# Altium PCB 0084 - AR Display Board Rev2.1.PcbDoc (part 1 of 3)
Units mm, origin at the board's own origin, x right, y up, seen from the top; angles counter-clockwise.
Board outline 127.7 x 27.2 mm, 4 copper layers (L1-TOP, L2-GND, L3-GND, L4-BOT), stack 1.571 mm thick; 141 components, 141 nets, 671 pads, 447 vias.
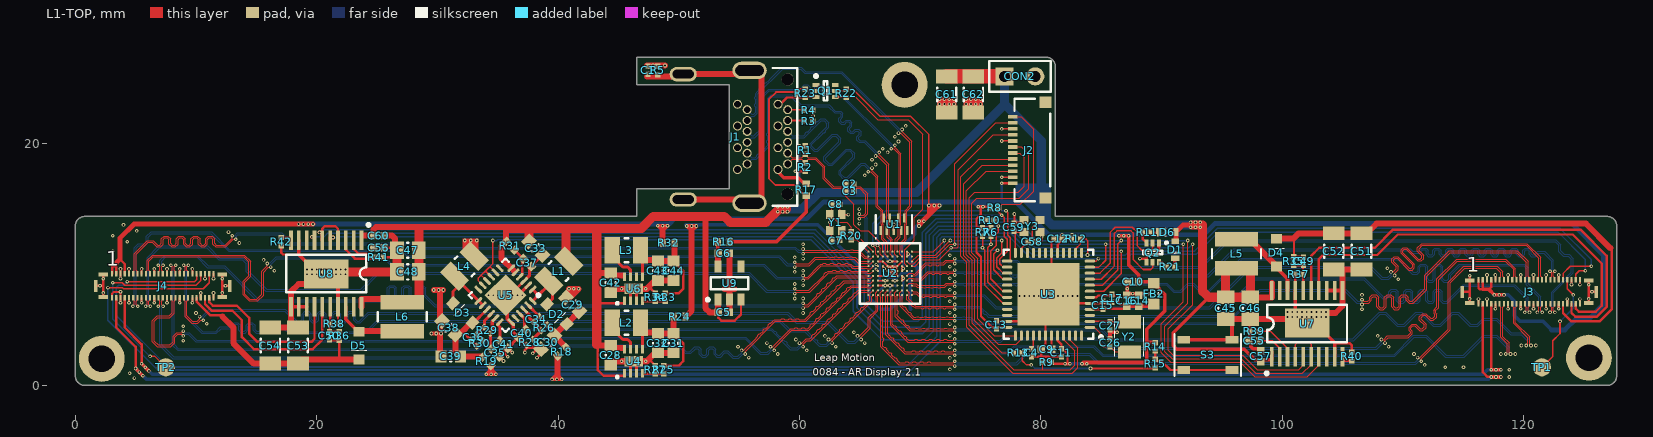
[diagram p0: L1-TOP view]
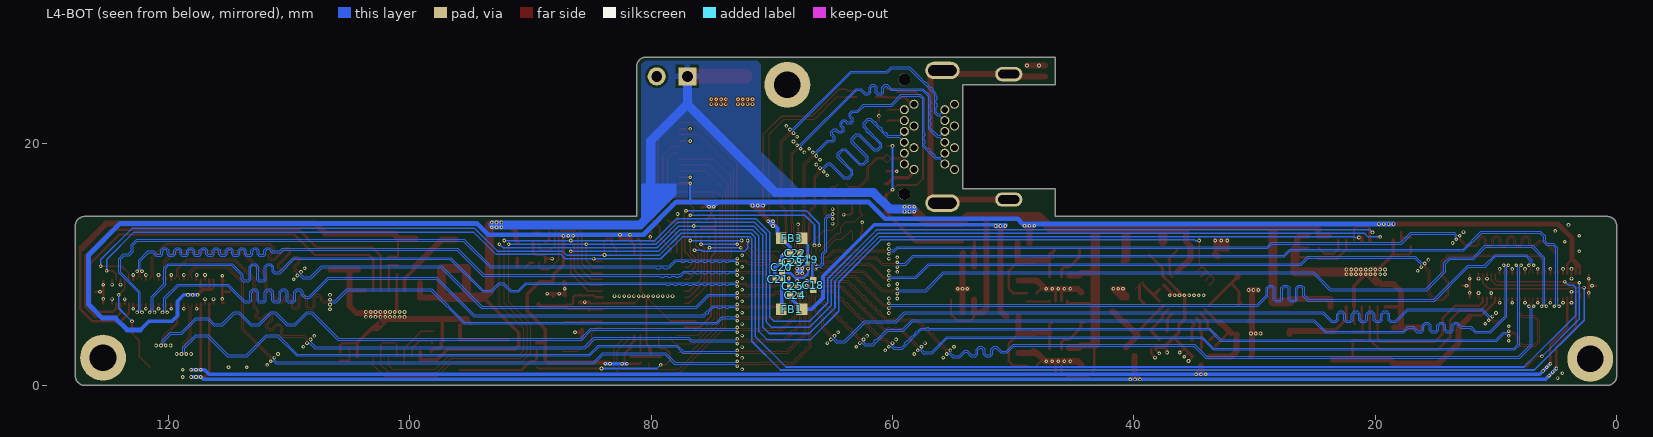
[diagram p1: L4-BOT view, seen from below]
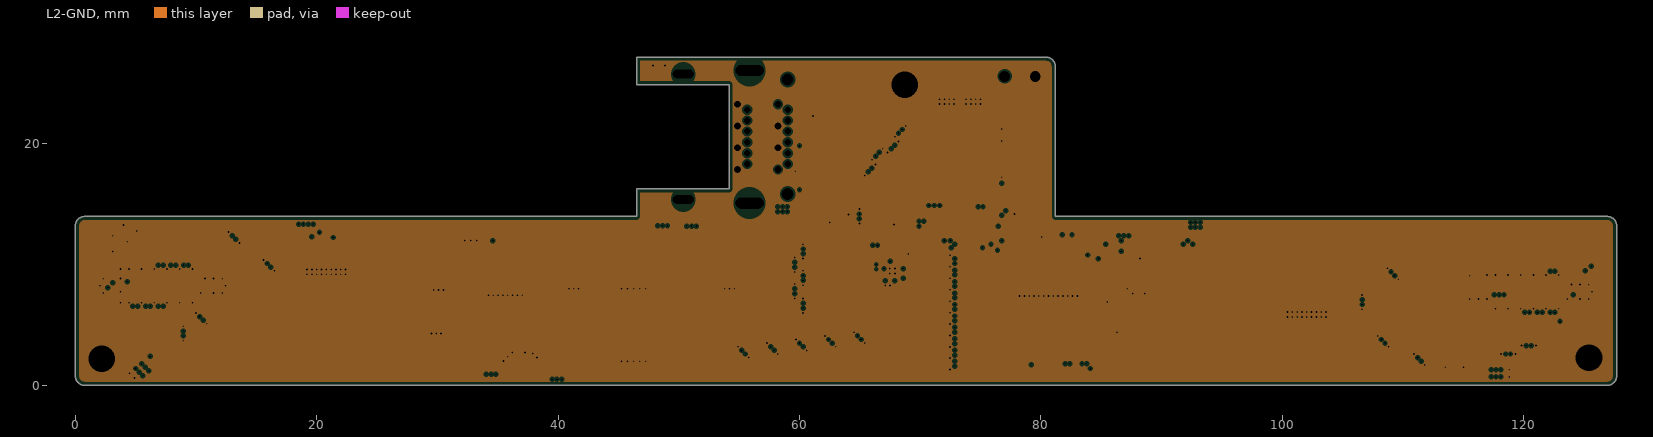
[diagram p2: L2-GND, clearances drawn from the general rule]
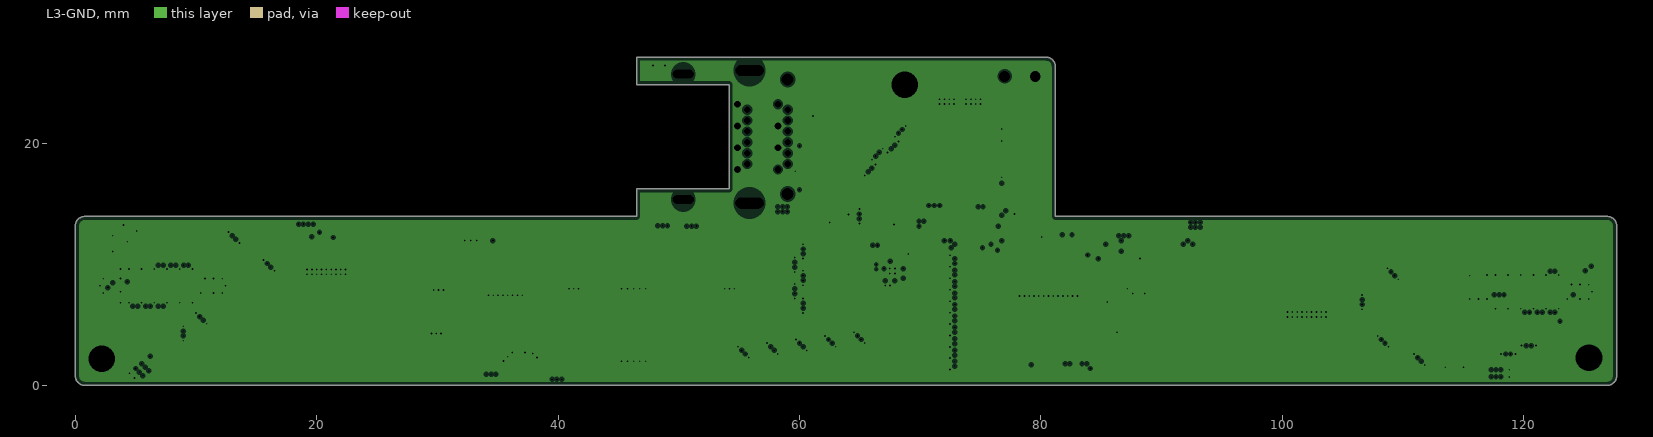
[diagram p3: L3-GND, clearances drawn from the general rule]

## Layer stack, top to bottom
Top Solder: solder mask 0.0102, Solder Resist, Dk 3.5
L1-TOP: signal copper 0.035
Dielectric1: core 0.175, FR-4, Dk 4.2
L2-GND: plane copper 0.036, net GND
Dielectric2: prepreg 1, Dk 4.2
L3-GND: plane copper 0.036, net GND
Dielectric 3: core 0.254, Dk 4.2
L4-BOT: signal copper 0.035
Bottom Solder: solder mask 0.0102, Solder Resist, Dk 3.5

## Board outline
0.8,0 cw(c0.8,0.8) 0,0.8 0,13.2 cw(c0.8,13.2) 0.8,14 46.5,14 46.5,16.3 54.16,16.3 54.16,24.9 46.5,24.9 46.5,27.2 80.4,27.2 cw(c80.4,26.4) 81.2,26.4 81.2,14 126.9,14 cw(c126.9,13.2) 127.7,13.2 127.7,0.8 cw(c126.9,0.8) 126.9,0

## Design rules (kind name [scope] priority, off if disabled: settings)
Clearance Clearance_1 [InComponent('CON2')] p1: gap=0.2
Clearance dp [(InDifferentialPairClass('All Differential Pairs')) vs InNet('GND')] p2: gap=0.076
Clearance [All] p3: gap=0.076
DiffPairsRouting [All] p1: maxlimit=0.076 minlimit=0.076 mostfreqgap=0.076 toplayer_minwidth=0.076 toplayer_maxwidth=0.076 toplayer_prefwidth=0.076 bottomlayer_minwidth=0.076 bottomlayer_maxwidth=0.076 bottomlayer_prefwidth=0.076 maxuncoupledlength=12.7
HoleSize [All] p1: absolutevalues=TRUE maxlimit=2.54 minlimit=0.1 maxpercent=80.000 minpercent=20.000
HoleToHoleClearance [All] p1: gap=0.25 allowstackedmicrovias=TRUE
MatchedLengths ML_MIPI_R [InNetClass('MIPI_R')] p1: tolerance=0.025 checknetsindiffpair=TRUE checkdiffpairvsdiffpair=TRUE checkothers=TRUE
MatchedLengths ML_MIPI_L [InNetClass('MIPI_L')] p2: tolerance=0.025 checknetsindiffpair=TRUE checkdiffpairvsdiffpair=TRUE checkothers=TRUE
MatchedLengths ML_DP_LANE [InNetClass('DP_LANE')] p3: tolerance=0.025 checknetsindiffpair=TRUE checkdiffpairvsdiffpair=TRUE checkothers=TRUE
MinimumAnnularRing [All] p1: minimumring=0.074
MinimumSolderMaskSliver [All] p1: minsoldermaskwidth=0.076
PlaneClearance [All] p1: clearance=0.15
PlaneConnect [All] p1: planeconnectstyle=Direct reliefexpansion=0 reliefentries=4 reliefconductorwidth=0.15 reliefairgap=0.15
PolygonConnect PolygonConnect_2 [InNet('GND') And OnLayer('L4-BOT')] p1: connectstyle=Relief reliefconductorwidth=0.254 reliefentries=4 polygonreliefangle="90 Angle" airgapwidth=0.254
PolygonConnect PolygonConnect_1 [InNet('5V') And OnLayer('L4-BOT')] p2: connectstyle=Relief reliefconductorwidth=0.5 reliefentries=4 polygonreliefangle="90 Angle" airgapwidth=0.2
PolygonConnect [All] p3: connectstyle=Direct reliefconductorwidth=0.254 reliefentries=4 polygonreliefangle="90 Angle" airgapwidth=0.254
RoutingVias [All] p1: holewidth=0.15 width=0.3 viastyle="Through Hole" minholewidth=0.15 minwidth=0.3 maxholewidth=0.711 maxwidth=1.27
SilkToSilkClearance [All] p1: silktosilkclearance=0.2
SilkToSolderMaskClearance SilkscreenOverComponentPads [IsPad] p1: minsilkscreentomaskgap=0.1 clearancetoexposedcopper=FALSE
SolderMaskExpansion [All] p1: expansion=0.025
UnpouredPolygon [All] p1: allowunpoured=FALSE
Width [All] p1: maxlimit=5 minlimit=0.076 preferedwidth=0.2 minimp=50.000000 maximp=50.000000 favimp=50.000000
21 further rules are at their usual default settings.

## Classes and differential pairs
component class "0084 - Connectors": C1 C61 C62 CON2 J1 J2 J3 J4 R1 R2 R3 R4 R5 R17 TP1 TP2 U1
component class "0084 - MCU": C2 C3 C4 C7 C8 C9 C10 C11 C12 C13 C14 C15 C16 C17 C18 C19 C20 C21 C22 C23 C24 C25 C26 C27 C58 C59 D1 D6 FB1 FB2 FB3 Q1 Q2 R6 R7 R8 R9 R10 R11 R12 R13 R14 R15 R20 R21 R22 R23 S3 U2 U3 Y1 Y2 Y3
component class "0084 - Power": C5 C6 C28 C29 C30 C31 C32 C33 C34 C35 C36 C37 C38 C39 C40 C41 C42 C43 C44 C45 C46 C47 C48 C49 C50 C51 C52 C53 C54 C55 C56 C57 C60 D2 D3 D4 D5 L1 L2 L3 L4 L5 L6 R16 R18 R19 R24 R25 R26 R27 R28 R29 R30 R31 R32 R33 R34 R35 R36 R37 R38 R39 R40 R41 R42 U4 U5 U6 U7 U8 U9
net class MIPI_R: MIPI_DSI10_0_N MIPI_DSI10_0_P MIPI_DSI10_1_N MIPI_DSI10_1_P MIPI_DSI10_2_N MIPI_DSI10_2_P MIPI_DSI10_3_N MIPI_DSI10_3_P MIPI_DSI10_C_N MIPI_DSI10_C_P MIPI_DSI11_0_N MIPI_DSI11_0_P MIPI_DSI11_1_N MIPI_DSI11_1_P MIPI_DSI11_2_N MIPI_DSI11_2_P MIPI_DSI11_3_N MIPI_DSI11_3_P MIPI_DSI11_C_N MIPI_DSI11_C_P
net class MIPI_L: MIPI_DSI00_0_N MIPI_DSI00_0_P MIPI_DSI00_1_N MIPI_DSI00_1_P MIPI_DSI00_2_N MIPI_DSI00_2_P MIPI_DSI00_3_N MIPI_DSI00_3_P MIPI_DSI00_C_N MIPI_DSI00_C_P MIPI_DSI01_0_N MIPI_DSI01_0_P MIPI_DSI01_1_N MIPI_DSI01_1_P MIPI_DSI01_2_N MIPI_DSI01_2_P MIPI_DSI01_3_N MIPI_DSI01_3_P MIPI_DSI01_C_N MIPI_DSI01_C_P
net class DP_LANE: DP_LANE0_N DP_LANE0_P DP_LANE1_N DP_LANE1_P DP_LANE2_N DP_LANE2_P DP_LANE3_N DP_LANE3_P
net class AUX: DP_AUX_CH_N DP_AUX_CH_P
differential pair AUX: +AUX_P -AUX_N
differential pair DP_AUX_CH: +DP_AUX_CH_P -DP_AUX_CH_N
differential pair DP_LANE0: +DP_LANE0_P -DP_LANE0_N
differential pair DP_LANE1: +DP_LANE1_P -DP_LANE1_N
differential pair DP_LANE2: +DP_LANE2_P -DP_LANE2_N
differential pair DP_LANE3: +DP_LANE3_P -DP_LANE3_N
differential pair MIPI_DSI00_0: +MIPI_DSI00_0_P -MIPI_DSI00_0_N
differential pair MIPI_DSI00_1: +MIPI_DSI00_1_P -MIPI_DSI00_1_N
differential pair MIPI_DSI00_2: +MIPI_DSI00_2_P -MIPI_DSI00_2_N
differential pair MIPI_DSI00_3: +MIPI_DSI00_3_P -MIPI_DSI00_3_N
differential pair MIPI_DSI00_C: +MIPI_DSI00_C_P -MIPI_DSI00_C_N
differential pair MIPI_DSI01_0: +MIPI_DSI01_0_P -MIPI_DSI01_0_N
differential pair MIPI_DSI01_1: +MIPI_DSI01_1_P -MIPI_DSI01_1_N
differential pair MIPI_DSI01_2: +MIPI_DSI01_2_P -MIPI_DSI01_2_N
differential pair MIPI_DSI01_3: +MIPI_DSI01_3_P -MIPI_DSI01_3_N
differential pair MIPI_DSI01_C: +MIPI_DSI01_C_P -MIPI_DSI01_C_N
differential pair MIPI_DSI10_0: +MIPI_DSI10_0_P -MIPI_DSI10_0_N
differential pair MIPI_DSI10_1: +MIPI_DSI10_1_P -MIPI_DSI10_1_N
differential pair MIPI_DSI10_2: +MIPI_DSI10_2_P -MIPI_DSI10_2_N
differential pair MIPI_DSI10_3: +MIPI_DSI10_3_P -MIPI_DSI10_3_N
differential pair MIPI_DSI10_C: +MIPI_DSI10_C_P -MIPI_DSI10_C_N
differential pair MIPI_DSI11_0: +MIPI_DSI11_0_P -MIPI_DSI11_0_N
differential pair MIPI_DSI11_1: +MIPI_DSI11_1_P -MIPI_DSI11_1_N
differential pair MIPI_DSI11_2: +MIPI_DSI11_2_P -MIPI_DSI11_2_N
differential pair MIPI_DSI11_3: +MIPI_DSI11_3_P -MIPI_DSI11_3_N
differential pair MIPI_DSI11_C: +MIPI_DSI11_C_P -MIPI_DSI11_C_N

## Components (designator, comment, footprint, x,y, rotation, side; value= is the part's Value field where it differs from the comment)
C1 "0.1uF" CAPC0201(0603)33_N 47.46,26.1 r270 top
C2 "0.1uF" CAPC0201(0603)33_N 64.16,16.7 r180 top
C3 "0.1uF" CAPC0201(0603)33_N 64.16,16.1 r180 top
C4 "0.1uF" CAPC0201(0603)33_N 79.2,2.7 r90 top
C5 "1.0uF" CAPC0402(1005)60_N 53.725,6.05 r0 top
C6 "1.0uF" CAPC0402(1005)60_N 53.725,10.95 r0 top
C7 "6pF" CAPC0201(0603)33_N 63,12 r180 top
C8 "6pF" CAPC0201(0603)33_N 63,15 r0 top
C9 "2.2uF" CAPC0402(1005)60_N 80.46,3 r180 top
C10 "1.0uF" CAPC0402(1005)60_N 87.66,8.6 r0 top
C11 "0.1uF" CAPC0201(0603)33_N 81.7,2.7 r90 top
C12 "0.1uF" CAPC0201(0603)33_N 81.425,12.15 r0 top
C13 "0.1uF" CAPC0201(0603)33_N 76.3,5.025 r270 top
C14 "1.0uF" CAPC0402(1005)60_N 88.1,7 r270 top
C15 "0.1uF" CAPC0201(0603)33_N 85.125,6.625 r270 top
C16 "1.0uF" CAPC0402(1005)60_N 87.1,7 r270 top
C17 "0.1uF" CAPC0201(0603)33_N 85.9,7.2 r90 top
C18 "1.0uF" CAPC0402(1005)60_L 66.56,8.3 r90 bottom
C19 "0.1uF" CAPC0201(0603)33_L 67.01,10.4 r90 bottom
C20 "1.0uF" CAPC0402(1005)60_L 69.16,9.8 r270 bottom
C21 "0.1uF" CAPC0201(0603)33_L 69.46,8.8 r180 bottom
C22 "1.0uF" CAPC0402(1005)60_L 68.06,10.95 r0 bottom
C23 "0.1uF" CAPC0201(0603)33_L 68.26,10.2 r0 bottom
C24 "1.0uF" CAPC0402(1005)60_L 68.06,7.45 r0 bottom
C25 "0.1uF" CAPC0201(0603)33_L 68.26,8.2 r0 bottom
C26 "18pF" CAPC0201(0603)33_N 85.725,3.55 r90 top
C27 "18pF" CAPC0201(0603)33_N 85.725,4.95 r270 top
C28 "10uF" CAPC0603(1608)100_N 44.36,2.5 r90 top
C29 "10uF" CAPC0603(1608)100_N 41.2,6.7 r315 top
C30 "10uF" CAPC0603(1608)100_N 39.144,3.567 r45 top
C31 "10uF" CAPC0603(1608)100_N 49.56,3.5 r90 top
C32 "10uF" CAPC0603(1608)100_N 48.26,3.5 r90 top
C33 "10uF" CAPC0603(1608)100_N 38.144,11.367 r135 top
C34 "15pF" CAPC0201(0603)33_N 38.19,5.487 r225 top
C35 "1.0uF" CAPC0402(1005)60_N 34.8,2.7 r315 top
C36 "12pF" CAPC0201(0603)33_N 33,4 r45 top
C37 "1.0uF" CAPC0402(1005)60_N 37.444,10.167 r135 top
C38 "10uF" CAPC0603(1608)100_N 30.944,4.767 r315 top
C39 "10uF" CAPC0603(1608)100_N 31.1,2.4 r0 top
C40 "10nF" CAPC0402(1005)60_N 37,4.3 r225 top
C41 "4.7nF" CAPC0402(1005)60_N 35.5,3.4 r315 top
C42 "10uF" CAPC0603(1608)100_N 44.36,8.5 r90 top
C43 "10uF" CAPC0603(1608)100_N 48.26,9.5 r90 top
C44 "10uF" CAPC0603(1608)100_N 49.56,9.5 r90 top
C45 "47uF" CAPC0805(2012)100_N 95.3,6.4 r90 top
C46 "47uF" CAPC0805(2012)100_N 97.35,6.4 r90 top
C47 "47uF" CAPC0805(2012)100_N 27.56,11.2 r0 top
C48 "47uF" CAPC0805(2012)100_N 27.56,9.4 r0 top
C49 "18pF" CAPC0201(0603)33_N 101.76,10.3 r270 top
C50 "18pF" CAPC0201(0603)33_N 21.06,4.1 r90 top
C51 "10uF" CAPC1206(3216)170_N 106.56,11.1 r90 top
C52 "10uF" CAPC1206(3216)170_N 104.26,11.1 r90 top
C53 "10uF" CAPC1206(3216)170_N 18.46,3.3 r270 top
C54 "10uF" CAPC1206(3216)170_N 16.16,3.3 r270 top
C55 "1.0uF" CAPC0402(1005)60_N 97.66,3.7 r180 top
C56 "1.0uF" CAPC0402(1005)60_N 25.16,11.4 r0 top
C57 "1.0uF" CAPC0402(1005)60_N 98.2,2.4 r270 top
C58 "12pF" CAPC0201(0603)33_N 79.26,11.9 r0 top
C59 "12pF" CAPC0201(0603)33_N 77.76,13.1 r90 top
C60 "1.0uF" CAPC0402(1005)60_N 25.16,12.4 r180 top
C61 "10uF" CAPC1206(3216)170_N 72.2,24.1 r90 top
C62 "10uF" CAPC1206(3216)170_N 74.4,24.1 r90 top
CON2 "CON2" CON2_100mil 78.26,25.6 r0 top
D1 "Value" Dialight_598-8010-107F 91.132,11.225 r270 top
D2 "SCHOTTKY" Toshiba_CUS10S40,H3F#1 39.9,5.9 r315 top
D3 "SCHOTTKY" Toshiba_CUS10S40,H3F#2 32.1,6 r315 top
D4 "SCHOTTKY" Toshiba_CUS10S40,H3F#2 99.5,11 r270 top
D5 "SCHOTTKY" Toshiba_CUS10S40,H3F#2 23.5,3.3 r90 top
D6 "Value" Dialight_598-8040-107F 90.475,12.7 r180 top
FB1 "Ferrite Bead" INDC1608X09N 68.36,6.3 r0 bottom
FB2 "Ferrite Bead" INDC1608X09N 89.36,7.6 r270 top
FB3 "Ferrite Bead" INDC1608X09N 68.36,12.2 r180 bottom
J1 "TE_2129320-3" TE_2129320-3 53.26,20.59 r270 top
J2 "FCI 10051922-1210ELF" "FCI 10051922-1210ELF" 79.51,19.5 r90 top locked
J3 "Kyocera_245863050024829" Kyocera_245863050024829 120.45,7.75 r0 top (schematic designator J2)
J4 "Kyocera_245863050024829" Kyocera_245863050024829 7.25,8.25 r0 top (schematic designator J2)
L1 "4.7uH" INDC2520X10N 40.044,9.467 r225 top
L2 "1uH" INDC2520X10N 45.66,5.2 r0 top
L3 "1uH" INDC2520X10N 45.66,11.2 r0 top
L4 "4.7uH" INDC2520X10N 32.244,9.867 r45 top
L5 "15uH" Coilcraft_XAL4040-153MEB 96.2,10.9 r90 top
L6 "15uH" Coilcraft_XAL4040-153MEB 27.1,5.7 r270 top
Q1 "NFET_DUAL" SOT-563 62.16,24.4 r0 top
Q2 "NFET_DUAL" SOT-563 89.26,11 r270 top
R1 "1M" RESC0201(0603)_N#1 60.46,19.49 r90 top
R2 "1M" RESC0201(0603)_N#2 60.46,18.09 r270 top
R3 "1M" RESC0201(0603)_N#1 60.76,21.9 r180 top
R4 "1M" RESC0201(0603)_N#1 60.76,22.8 r180 top
R5 "1M" RESC0201(0603)_N#1 48.26,26.1 r270 top
R6 "4.7K" RESC0201(0603)_N#1 75.86,12.7 r90 top
R7 "4.7K" RESC0201(0603)_N#1 75.16,12.7 r90 top
R8 "10K" RESC0201(0603)_N#1 76.16,14.7 r180 top
R9 "10K" RESC0201(0603)_N#1 80.5,1.9 r0 top
R10 "10K" RESC0201(0603)_N#1 75.76,13.7 r180 top
R11 "1K" RESC0201(0603)_N#1 88.8,12.675 r180 top
R12 "10K" RESC0201(0603)_N#1 82.925,12.15 r180 top
R13 "1K" RESC0201(0603)_N#1 78.1,2.7 r0 top
R14 "10K" RESC0201(0603)_N#1 89.46,3.2 r90 top
R15 "1K" RESC0201(0603)_N#1 89.46,1.8 r270 top
R16 "0R" RESC0402(1005)_N 53.725,11.89 r0 top
R17 "0R" RESC0402(1005)_N 60.56,16.2 r270 top
R18 "0R" RESC0402(1005)_N 40.3,2.8 r225 top
R19 "0R" RESC0402(1005)_N 34.1,2 r315 top
R20 "1M" RESC0201(0603)_N#1 64.3,12.4 r270 top
R21 "1K" RESC0201(0603)_N#1 90.725,9.825 r180 top
R22 "10K" RESC0201(0603)_N#1 63.86,24.2 r90 top
R23 "10K" RESC0201(0603)_N#1 60.46,24.2 r270 top
R24 "0R" RESC0402(1005)_N 50.06,5.7 r0 top
R25 "36.5K" RESC0201(0603)_N#1 48.76,1.3 r90 top
R26 "560K" RESC0201(0603)_N#1 38.844,4.767 r225 top
R27 "30K" RESC0201(0603)_N#1 48.06,1.3 r270 top
R28 "150K" RESC0201(0603)_N#1 37.644,3.567 r45 top
R29 "715K" RESC0201(0603)_N#1 34.144,4.567 r135 top
R30 "620K" RESC0201(0603)_N#1 33.5,3.5 r45 top
R31 "10R" RESC0402(1005)_N 36.044,11.567 r315 top
R32 "0R" RESC0402(1005)_N 49.16,11.8 r180 top
R33 "90.9K" RESC0201(0603)_N#1 48.86,7.3 r90 top
R34 "30K" RESC0201(0603)_N#1 48.06,7.3 r270 top
R35 "750K" RESC0201(0603)_N#1 100.96,10.3 r270 top
R36 "750K" RESC0201(0603)_N#1 21.86,4.1 r90 top
R37 "130K" RESC0201(0603)_N#1 101.36,9.2 r0 top
R38 "130K" RESC0201(0603)_N#1 21.46,5.1 r180 top
R39 "49.9K" RESC0201(0603)_N#1 97.66,4.5 r0 top
R40 "62K" RESC0201(0603)_N#1 105.76,2.4 r270 top
R41 "49.9K" RESC0201(0603)_N#1 25.16,10.6 r180 top
R42 "62K" RESC0201(0603)_N#1 17.06,11.9 r90 top
S3 "SW-SPST" ALPS_SKRPABE010 93.825,2.525 r0 top
TP1 "TestPoint" TestPointRnd-1_5mm#1 121.5,1.5 r0 top
TP2 "TestPoint" TestPointRnd-1_5mm#2 7.9,1.5 r90 top
U1 "Semtech_RCLAMP7528T.TNT" Semtech_RCLAMP7528T.TNT 67.82,13.35 r90 top locked
U2 "Analogix_ANX7350" Analogix_ANX7350 67.5,9.275 r0 top
U3 "Atmel_ATSAMD21G18A-MU" Atmel_ATSAMD21G18A-MU 80.625,7.55 r0 top
U4 "TI_TLV62080" TI_TLV62080 46.26,2 r90 top
U5 "TI_TPS65131-Q1" TI_TPS65131-Q1 35.644,7.467 r225 top
U6 "TI_TLV62080" TI_TLV62080 46.26,8 r90 top
U7 "TI_TPS61194-Q1" TI_TPS61194-Q1 102.072,5.15 r0 top
U8 "TI_TPS61194-Q1" TI_TPS61194-Q1 20.775,9.231 r180 top
U9 "TI_LP5907_SOT23" TI_LP5907_SOT23 54.2,8.475 r90 top
Y1 "Crystal" Abracon_ABM11 63,13.5 r270 top
Y2 "Crystal_2pin" Abracon_ABS07 87.325,4.025 r270 top
Y3 "Crystal" Abracon_ABM11 79.26,13.2 r0 top

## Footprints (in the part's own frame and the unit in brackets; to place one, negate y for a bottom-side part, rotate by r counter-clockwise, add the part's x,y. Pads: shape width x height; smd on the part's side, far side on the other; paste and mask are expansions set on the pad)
Abracon_ABM11 [mm]
  rect 0.75x0.65 smd: 1(-0.65,-0.5) 2(0.65,-0.5) 3(0.65,0.5) 4(-0.65,0.5)
  body extent -1,-0.8 1,0.8, height 0.59
Abracon_ABS07 [mm]
  rect 1.1x1.9 smd: 0(-1.25,0) 1(1.25,0)
  silkscreen extent -1.6,-1.2 1.6,1.2, body extent -1.6,-0.75 1.6,0.75, height 0.9
ALPS_SKRPABE010 [mm]
  rect 1.05x0.65 smd: 1(-2,1.25) 1(2,1.25) 2(-2,-1.25) 2(2,-1.25)
  silkscreen extent -2.75,-1.75 2.75,1.75, body extent -2.3,-1.6 2.3,1.6, height 2.5
Analogix_ANX7350 [mm] "BGA, 100-Leads, Body 5.00x5.00mmx0.91mm, Pitch 0.40mm"
  round 0.171 smd: A1(-1.8,1.8) A2(-1.4,1.8) A3(-1,1.8) A4(-0.6,1.8) A5(-0.2,1.8) A6(0.2,1.8) A7(0.6,1.8) A8(1,1.8) A9(1.4,1.8) A10(1.8,1.8) B1(-1.8,1.4) B2(-1.4,1.4) B3(-1,1.4) B4(-0.6,1.4) B5(-0.2,1.4) B6(0.2,1.4) B7(0.6,1.4) B8(1,1.4) B9(1.4,1.4) B10(1.8,1.4) C1(-1.8,1) C2(-1.4,1) C3(-1,1) C4(-0.6,1) C5(-0.2,1) C6(0.2,1) C7(0.6,1) C8(1,1) C9(1.4,1) C10(1.8,1) D1(-1.8,0.6) D2(-1.4,0.6) D3(-1,0.6) D4(-0.6,0.6) D5(-0.2,0.6) D6(0.2,0.6) D7(0.6,0.6) D8(1,0.6) D9(1.4,0.6) D10(1.8,0.6) E1(-1.8,0.2) E2(-1.4,0.2) E3(-1,0.2) E4(-0.6,0.2) E5(-0.2,0.2) E6(0.2,0.2) E7(0.6,0.2) E8(1,0.2) E9(1.4,0.2) E10(1.8,0.2) F1(-1.8,-0.2) F2(-1.4,-0.2) F3(-1,-0.2) F4(-0.6,-0.2) F5(-0.2,-0.2) F6(0.2,-0.2) F7(0.6,-0.2) F8(1,-0.2) F9(1.4,-0.2) F10(1.8,-0.2) G1(-1.8,-0.6) G2(-1.4,-0.6) G3(-1,-0.6) G4(-0.6,-0.6) G5(-0.2,-0.6) G6(0.2,-0.6) G7(0.6,-0.6) G8(1,-0.6) G9(1.4,-0.6) G10(1.8,-0.6) H1(-1.8,-1) H2(-1.4,-1) H3(-1,-1) H4(-0.6,-1) H5(-0.2,-1) H6(0.2,-1) H7(0.6,-1) H8(1,-1) H9(1.4,-1) H10(1.8,-1) J1(-1.8,-1.4) J2(-1.4,-1.4) J3(-1,-1.4) J4(-0.6,-1.4) J5(-0.2,-1.4) J6(0.2,-1.4) J7(0.6,-1.4) J8(1,-1.4) J9(1.4,-1.4) J10(1.8,-1.4) K1(-1.8,-1.8) K2(-1.4,-1.8) K3(-1,-1.8) K4(-0.6,-1.8) K5(-0.2,-1.8) K6(0.2,-1.8) K7(0.6,-1.8) K8(1,-1.8) K9(1.4,-1.8) K10(1.8,-1.8)
  silkscreen extent -2.5,-2.5 2.5,2.5, body extent -2.5,-2.5 2.5,2.5, height 0.91
Atmel_ATSAMD21G18A-MU [mm]
  oval 0.85x0.25 smd: 1(3.425,-2.75) 2(3.425,-2.25) 3(3.425,-1.75) 4(3.425,-1.25) 5(3.425,-0.75) 6(3.425,-0.25) 7(3.425,0.25) 8(3.425,0.75) 9(3.425,1.25) 10(3.425,1.75) 11(3.425,2.25) 12(3.425,2.75) 25(-3.425,2.75) 26(-3.425,2.25) 27(-3.425,1.75) 28(-3.425,1.25) 29(-3.425,0.75) 30(-3.425,0.25) 31(-3.425,-0.25) 32(-3.425,-0.75) 33(-3.425,-1.25) 34(-3.425,-1.75) 35(-3.425,-2.25) 36(-3.425,-2.75)
  oval 0.25x0.85 smd: 13(2.75,3.425) 14(2.25,3.425) 15(1.75,3.425) 16(1.25,3.425) 17(0.75,3.425) 18(0.25,3.425) 19(-0.25,3.425) 20(-0.75,3.425) 21(-1.25,3.425) 22(-1.75,3.425) 23(-2.25,3.425) 24(-2.75,3.425) 37(-2.75,-3.425) 38(-2.25,-3.425) 39(-1.75,-3.425) 40(-1.25,-3.425) 41(-0.75,-3.425) 42(-0.25,-3.425) 43(0.25,-3.425) 44(0.75,-3.425) 45(1.25,-3.425) 46(1.75,-3.425) 47(2.25,-3.425) 48(2.75,-3.425)
  rect 5.15x5.15 smd: 49(0,0)
  silkscreen extent -3.7,-3.7 4.47,3.7, body extent -3.55,-3.55 3.55,3.55, height 0.9
CAPC0201(0603)33_L [mm] "Chip Capacitor, Body 0.6x0.3mm, Height 0.33mm, IPC High Density"
  rect 0.36x0.32 smd: 1(-0.28,0) 2(0.28,0)
  body extent -0.32,-0.17 0.32,0.17, height 0.33
CAPC0201(0603)33_N [mm] "Chip Capacitor, Body 0.6x0.3mm, Height 0.33mm, IPC Medium Density"
  rect 0.46x0.42 smd: 1(-0.33,0) 2(0.33,0)
  body extent -0.31,-0.16 0.32,0.17, height 0.33
CAPC0402(1005)60_L [mm] "Chip Capacitor, Body 1.0x0.5mm, Height 0.6mm, IPC High Density"
  rect 0.52x0.52 smd: 1(-0.4,0) 2(0.4,0)
  body extent -0.55,-0.3 0.55,0.3, height 0.6
CAPC0402(1005)60_N [mm] "Chip Capacitor, Body 1.0x0.5mm, Height 0.6mm, IPC Medium Density"
  rect 0.62x0.62 smd: 1(-0.45,0) 2(0.45,0)
  body extent -0.55,-0.3 0.55,0.3, height 0.6
CAPC0603(1608)100_N [mm] "Chip Capacitor, Body 1.6x0.8mm, Height 1.0mm, IPC Medium Density"
  rect 0.9x1 smd: 1(-0.8,0) 2(0.8,0)
  silkscreen extent -0.05,-0.4 0.05,0.4, body extent -0.87,-0.48 0.88,0.47, height 1
CAPC0805(2012)100_N [mm] "Chip Capacitor, Body 2.0x1.2mm, Height 1.0mm, IPC Medium Density"
  rect 1.15x1.45 smd: 1(-0.9,0) 2(0.9,0)
  silkscreen extent -0.05,-0.62 0.05,0.63, body extent -1.1,-0.72 1.1,0.73, height 1
CAPC1206(3216)170_N [mm] "Chip Capacitor, Body 3.2x1.6mm, Height 1.7mm, IPC Medium Density"
  rect 1.15x1.8 smd: 1(-1.5,0) 2(1.5,0)
  silkscreen extent -0.55,-0.8 0.55,0.8, body extent -1.7,-0.9 1.7,0.9, height 1.7
Coilcraft_XAL4040-153MEB [mm] "Chip Inductor, 2-Leads, Body 4.00x4.00mm, IPC Medium Density"
  rect 1.2x3.6 smd: 1(-1.2,0) 2(1.2,0)
  silkscreen extent -0.38,-2.03 0.38,2.03, body extent -2.1,-2.1 2.1,2.1, height 4.1
CON2_100mil [mm]
  rect 1.5x1.5 hole 0.9: 1(-1.27,0)
  round 1.5 hole 0.9: 2(1.27,0)
  silkscreen extent -2.54,-1.27 2.54,1.27
Dialight_598-8010-107F [mm]
  rect 0.45x0.65 smd: A(-0.7,0)
  rect 0.45x0.7 smd: K(0.7,0)
  body extent -0.81,-0.4 0.81,0.39, height 0.71
Dialight_598-8040-107F [mm]
  rect 0.45x0.65 smd: A(-0.7,0)
  rect 0.45x0.7 smd: K(0.7,0)
  body extent -0.81,-0.4 0.81,0.39, height 0.71
"FCI 10051922-1210ELF" [mm]
  rect 0.95x1 smd: 0(-3.975,-0.85) 0(3.975,-0.85)
  rect 0.3x0.8 smd: 1(-2.75,1.85) 2(-2.25,1.85) 3(-1.75,1.85) 4(-1.25,1.85) 5(-0.75,1.85) 6(-0.25,1.85) 7(0.25,1.85) 8(0.75,1.85) 9(1.25,1.85) 10(1.75,1.85) 11(2.25,1.85) 12(2.75,1.85)
  silkscreen extent -4.25,-1.25 4.25,1.7, body extent -4.25,-1.75 4.25,2, height 1.27
INDC1608X09N [mm] "Chip Inductor, 2-Leads, Body 1.60x0.80mm, IPC Medium Density"
  rect 0.89x0.96 smd: 1(-0.855,0) 2(0.855,0)
  body extent -0.87,-0.48 0.87,0.47, height 0.95
INDC2520X10N [mm] "Chip Inductor, 2-Leads, Body 2.50x2.00mm, IPC Medium Density"
  rect 1.27x2.2 smd: 1(-1.165,0) 2(1.165,0)
  silkscreen extent -0.15,-1 0.15,1, body extent -1.35,-1.1 1.35,1.1, height 1
Kyocera_245863050024829 [mm] "50 pin female connector 0.35mm pitch"
  rect 0.18x0.47 smd: 1(-4.2,-1) 2(-4.2,1) 3(-3.85,-1) 4(-3.85,1) 5(-3.5,-1) 6(-3.5,1) 7(-3.15,-1) 8(-3.15,1) 9(-2.8,-1) 10(-2.8,1) 11(-2.45,-1) 12(-2.45,1) 13(-2.1,-1) 14(-2.1,1) 15(-1.75,-1) 16(-1.75,1) 17(-1.4,-1) 18(-1.4,1) 19(-1.05,-1) 20(-1.05,1) 21(-0.7,-1) 22(-0.7,1) 23(-0.35,-1) 24(-0.35,1) 25(0,-1) 26(0,1) 27(0.35,-1) 28(0.35,1) 29(0.7,-1) 30(0.7,1) 31(1.05,-1) 32(1.05,1) 33(1.4,-1) 34(1.4,1) 35(1.75,-1) 36(1.75,1) 37(2.1,-1) 38(2.1,1) 39(2.45,-1) 40(2.45,1) 41(2.8,-1) 42(2.8,1) 43(3.15,-1) 44(3.15,1) 45(3.5,-1) 46(3.5,1) 47(3.85,-1) 48(3.85,1) 49(4.2,-1) 50(4.2,1)
  rect 0.3x1 smd: M(-5.55,0) M(5.55,0)
  rect 0.8x0.35 smd: M(-4.925,-0.935) M(-4.925,0.935) M(4.925,-0.935) M(4.925,0.935)
RESC0201(0603)_N#1 [mm] "Chip Resistor, Body 0.6x0.3mm, IPC Medium Density"
  rect 0.45x0.45 smd: 1(-0.35,0) 2(0.35,0)
  body extent -0.31,-0.16 0.31,0.16, height 0.3
RESC0201(0603)_N#2 [mm] "Chip Resistor, Body 0.6x0.3mm, IPC Medium Density"
  rect 0.45x0.45 smd: 1(0.35,0) 2(-0.35,0)
  body extent -0.31,-0.16 0.31,0.16, height 0.3
RESC0402(1005)_N [mm] "Chip Resistor, Body 1.0x0.5mm, IPC Medium Density"
  rect 0.55x0.65 smd: 1(-0.5,0) 2(0.5,0)
  body extent -0.52,-0.27 0.53,0.28, height 0.4
Semtech_RCLAMP7528T.TNT [mm] "SON, 10-Leads, Body 2.60x1.10mm, Pitch 0.50mm, IPC Medium Density"
  rect 0.75x0.2 smd mask+0: 1(-0.52,1.1) 2(-0.52,0.6) 3(-0.52,0) 4(-0.52,-0.6) 5(-0.52,-1.1) 6(0.52,-0.85) 7(0.52,-0.35) 8(0.52,0.35) 9(0.52,0.85)
  silkscreen extent -1.2,-1.5 0.75,1.55, body extent -0.6,-1.35 0.6,1.35, height 0.43
SOT-563 [mm] "SOTFL, 6-Leads, Body 1.60x1.60mm, Pitch 0.50mm, IPC Medium Density"
  rect 0.55x0.33 smd: 1(-0.8,0.5) 2(-0.8,0) 3(-0.8,-0.5) 4(0.8,-0.5) 5(0.8,0) 6(0.8,0.5)
  silkscreen extent -0.92,-0.8 0.15,1.35, body extent -0.6,-0.8 0.6,0.8, height 0.5
TE_2129320-3 [mm] "Mini Displayport"
  oval 1.45x2.85 hole 0.9 slot 2.35 at 90 deg: 0(-5.5,2.605) 0(5.49,2.605)
  oval 1.2x2.25 hole 0.7 slot 1.74 at 90 deg: 0(-5.2,-2.895) 0(5.19,-2.895)
  round 0.75 hole 0.55: 1(-2.7,1.605) 2(-2.7,4.955) 3(-2.25,2.405) 4(-2.25,5.755) 5(-1.35,2.405) 6(-1.35,5.755) 7(-0.9,1.605) 8(-0.9,4.955) 9(-0.45,2.405) 10(-0.45,5.755) 11(0.45,2.405) 12(0.45,5.755) 13(0.9,1.605) 14(0.9,4.955) 15(1.35,2.405) 16(1.35,5.755) 17(2.25,2.405) 18(2.25,5.755) 19(2.7,1.605) 20(2.7,4.955)
  round 1 hole 1 unplated: ""(-4.75,5.755) ""(4.74,5.755)
  silkscreen extent -5.7,4.5 5.7,6.56, body extent -5.67,-6.34 5.73,6.31, height 4.23
TestPointRnd-1_5mm#1 [mm]
  round 1.5 smd paste-1: 0(0,0)
TestPointRnd-1_5mm#2 [mm]
  round 1.5 smd paste-1: 0(0,0.4)
TI_LP5907_SOT23 [mm] "SOT23, 5-Leads, Body 2.90x2.80mm, Pitch 0.95mm, IPC Medium Density"
  rect 1x0.6 smd: 1(-1.375,0.95) 2(-1.375,0) 3(-1.375,-0.95) 4(1.375,-0.95) 5(1.375,0.95)
  silkscreen extent -1.5,-1.55 0.5,1.92, body extent -0.88,-1.52 0.87,1.53, height 1.45
TI_TLV62080 [mm] "SON, 8-Leads, Body 2.00x2.00mm, Pitch 0.50mm, Thermal Pad 1.55x0.85mm, IPC Medium Density"
  rect 0.7x0.25 smd: 1(-0.995,0.75) 2(-0.995,0.25) 3(-0.995,-0.25) 4(-0.995,-0.75) 5(0.995,-0.75) 6(0.995,-0.25) 7(0.995,0.25) 8(0.995,0.75)
  rect 0.85x1.55 smd: 9(0,0)
  silkscreen extent -1.4,1.26 -1.2,1.46, body extent -1.05,-1.05 1.05,1.05, height 0.8
TI_TPS61194-Q1 [mm] "20 TSSOP WITH P.PAD"
  rect 0.3x1.6 smd: 1(-2.943,-2.785) 2(-2.293,-2.785) 3(-1.643,-2.785) 4(-0.993,-2.785) 5(-0.343,-2.785) 6(0.307,-2.785) 7(0.957,-2.785) 8(1.607,-2.785) 9(2.257,-2.785) 10(2.907,-2.785) 11(2.907,2.715) 12(2.257,2.715) 13(1.607,2.715) 14(0.957,2.715) 15(0.307,2.715) 16(-0.343,2.715) 17(-0.993,2.715) 18(-1.643,2.715) 19(-2.293,2.715) 20(-2.943,2.715)
  rect 3.7x2.4 smd: 21(-0.022,0.009)
  silkscreen extent -3.5,-4.27 3.28,1.52, body extent -3.3,-1.52 3.3,1.52, height 1.1
TI_TPS65131-Q1 [mm]
  oval 0.8x0.25 smd: 1(-1.925,1.25) 2(-1.925,0.75) 3(-1.925,0.25) 4(-1.925,-0.25) 5(-1.925,-0.75) 6(-1.925,-1.25) 13(1.925,-1.25) 14(1.925,-0.75) 15(1.925,-0.25) 16(1.925,0.25) 17(1.925,0.75) 18(1.925,1.25)
  oval 0.25x0.8 smd: 7(-1.25,-1.925) 8(-0.75,-1.925) 9(-0.25,-1.925) 10(0.25,-1.925) 11(0.75,-1.925) 12(1.25,-1.925) 19(1.25,1.925) 20(0.75,1.925) 21(0.25,1.925) 22(-0.25,1.925) 23(-0.75,1.925) 24(-1.25,1.925)
  rect 2.45x2.45 smd: 25(0,0)
  silkscreen extent -2.15,-2.15 2.15,2.15, body extent -2,-2 2,2, height 1
Toshiba_CUS10S40,H3F#1 [mm] "SODFL, 2-Leads, Body 1.25x2.50mm, IPC Medium Density"
  rect 0.8x0.9 smd: A(-1.15,0) K(1.15,0)
  silkscreen extent 0.38,-0.64 0.38,0.64, body extent -0.9,-0.67 0.9,0.67, height 1
Toshiba_CUS10S40,H3F#2 [mm] "SODFL, 2-Leads, Body 1.25x2.50mm, IPC Medium Density"
  rect 0.8x0.9 smd: A(1.15,0) K(-1.15,0)
  silkscreen extent -0.38,-0.64 -0.38,0.63, body extent -0.9,-0.67 0.9,0.67, height 1

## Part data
C1 C2 C3 C4 C11 C12 C13 C15 C17 C19 C21 C23 C25: library part CAP_0060, "Capacitor, 0.1uF, 10V, 10%, 0201, Ceramic, X5R"
C5 C6 C10 C14 C16 C18 C20 C22 C24 C35 C37 C40 C41 C55 C56 C57 C60: library part CAP_0023, "Capacitor, 1.0uF, 10V, 10%, 0402, Ceramic, X5R"
C7 C8: library part CAP_0064, "Capacitor, 6pF, 50V, 0.1pF, 0201, Ceramic, C0G(NP0)"
C9: library part CAP_0016, "Capacitor, 2.2uF, 6.3V, 20%, 0402, Ceramic, X5R"
C26 C27 C49 C50: library part CAP_0066, "Capacitor, 18pF, 50V, 2%, 0201, Ceramic, C0G(NP0)"
C28 C29 C30 C31 C32 C33 C38 C39 C42 C43 C44: library part CAP_0069, "Capacitor, 10uF, 10V, 10%, 0603, Ceramic, X5R"
C34: library part CAP_0067, "Capacitor, 15pF, 50V, 2%, 0201, Ceramic, C0G(NP0)"
C36 C58 C59: library part CAP_0065, "Capacitor, 12pF, 50V, 2%, 0201, Ceramic, C0G(NP0)"
C45 C46 C47 C48: library part CAP_0050, "Capacitor, 47uF, 10V, 20%, 0805, Ceramic, X5R"
C51 C52 C53 C54 C61 C62: library part CAP_0068, "Capacitor, 10uF, 50V, 10%, 1206, Ceramic, X7R"
CON2: library part CONN_0036, "Connector, Generic, Header, 2POS, 2.54mm"
D1: library part LED_0017, "LED, 635nm, 140deg, , 20mA, , 1.6mm x 0.8mm, -30C - 85C"
D2 D3 D4 D5: library part DIODE_0020, "Diode, -40C - 150C, SOD-323"
D6: library part LED_0034, "LED, 593nm, 140deg, , 20mA, , 1.6mm x 0.8mm, -30C - 85C"
FB1 FB2 FB3: library part FB_0001, "FERRITE CHIP BEAD 600 OHM SMD"
J1: library part CONN_0094, "Connector, TE Connectivity, Receptacle, 20POS, 0.9mm"
J2: library part CONN_0043, "Connector, FCI, Right Angle, 12POS, 0.5mm"
J3 J4: "245863050024829"
L1 L4: library part IND_0023, "FIXED IND 4.7UH 1.4A 216 MOHM"
L2 L3: library part IND_0001, "INDUCTOR 1.0UH 20% 1600MA 1008"
L5 L6: library part IND_0026, "Fixed Inductors XAL4040 AEC-Q200 15 uH 20 % 2.8 A"
Q1 Q2: library part NFET_0009, "Transistor, NFET_DUAL, 2.2Ohm, 200mA, 120mW, 	SOT-563, -55C - 150C"
R1 R2 R3 R4 R5 R20: library part RES_0178, "Resistor, 1M, 1/20W, 1%, 0201"
R6 R7: library part RES_0040, "Resistor, 4.7K, 1/20W, 1%, 0201"
R8 R9 R10 R12 R14 R22 R23: library part RES_0014, "Resistor, 10K, 1/20W, 5%, 0201"
R11 R13 R15 R21: library part RES_0036, "Resistor, 1K, 1/20W, 5%, 0201"
R16 R17 R18 R19 R24 R32: library part RES_0006, "Resistor, 0R, 1/10W, Jumper, 0402"
R25: library part RES_0176, "Resistor, 36.5K, 1/20W, 1%, 0201"
R26: library part RES_0194, "Resistor, 560K, 1/20W, 1%, 0201"
R27 R34: library part RES_0175, "Resistor, 30K, 1/20W, 1%, 0201"
R28: library part RES_0173, "Resistor, 150K, 1/20W, 1%, 0201"
R29: library part RES_0195, "Resistor, 715K, 1/20W, 1%, 0201"
R30: library part RES_0174, "Resistor, 620K, 1/20W, 1%, 0201"
R31: library part RES_0094, "Resistor, 10R, 1/10W, 1%, 0402"
R33: library part RES_0177, "Resistor, 90.9K, 1/20W, 1%, 0201"
R35 R36: library part RES_0169, "Resistor, 750K, 1/20W, 1%, 0201"
R37 R38: library part RES_0170, "Resistor, 130K, 1/20W, 1%, 0201"
R39 R41: library part RES_0067, "Resistor, 49.9K, 1/20W, 1%, 0201"
R40 R42: library part RES_0071, "Resistor, 62K, 1/20W, 1%, 0201"
S3: library part SWT_0006, "Switch, SPST-NO, Button, 4.6mm x 3.2mm"
TP1 TP2: library part MISC_0052, "Misc, TestPoint"
U1: library part IC_0201, "TVS DIODE 5VWM 15VC SLP2611N9T"
U2: library part IC_0196, "DisplayPort 1.4-to-Dual MIPI Output Converter"
U3: library part IC_0197, "IC MCU 32BIT 256KB FLASH 48QFN"
U4 U6: library part IC_0195, "IC REG BUCK ADJ 1.2A SYNC 8WSON"
U5: library part IC_0199, "IC REG BCK BST INV ADJ DL 24VQFN"
U7 U8: library part IC_0200, "IC LED DRIVER 20TSSOP"
U9: library part IC_0118, "3.3 V LDO Voltage Regulators 250mA Ultra-Lo Noise LDO Reg"
Y1: library part XTAL_0025, "Crystal, 24MHz, 6pF, 4-SMD (2x1.6)"
Y2: library part XTAL_0023, "Crystal, 32.768KHz, 12.5pF, 2-SMD(3.2x1.5)"
Y3: library part XTAL_0024, "Crystal, 16MHz, 10pF, 4-SMD (2x1.6)"

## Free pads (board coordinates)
  round 3.8 hole 2.2: 0(2.2,2.2) 0(68.7,24.9) 0(125.4,2.3)

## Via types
v1: diameter 0.3, hole 0.15, L1-TOP to L4-BOT, tented both sides, 445 vias
v2: diameter 0.25, hole 0.1, L1-TOP to L4-BOT, tented both sides, 2 vias

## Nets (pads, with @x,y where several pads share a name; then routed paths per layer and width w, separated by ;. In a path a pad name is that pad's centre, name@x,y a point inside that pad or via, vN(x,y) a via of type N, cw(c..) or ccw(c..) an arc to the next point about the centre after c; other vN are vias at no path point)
1V: C24.2 C25.2 FB1.1 R24.2 U2.F8 U2.G8 | length 35.5
  L1-TOP w0.152: U2.G8@68.5,8.675 68.6,8.775 v1(68.6,8.875) 68.6,8.975 U2.F8@68.5,9.075 U2.G8@68.5,8.675
  L1-TOP w0.3: v1(50.66,13.2) 51.06,12.8 v1(51.46,13.2) v1(51.06,13.2) v1(50.66,13.2)
  L1-TOP w0.5: R24.2@50.56,5.7 51.06,6.2 51.06,12.8 51.06,13
  L4-BOT w0.2: C24.2@68.46,7.45 68.54,7.53 C25.2@68.54,8.2 68.6,8.26 v1(68.6,8.875)
  L4-BOT w0.3: 51.6,13.3 51.5,13.2 v1(51.46,13.2) v1(51.06,13.2) v1(50.66,13.2) 50.6,13.26 50.6,13.3 61.5,13.3 65.76,9.04 65.76,7.24 66.7,6.3 FB1.1@67.305,6.3 ; FB1.1@67.205,6.4 FB1.1@67.305,6.3 ; C24.2@68.46,7.45 68.46,7.255 FB1.1@67.505,6.3 FB1.1@67.305,6.3
1V8: C10.2 C11.2 C12.2 C13.2 C22.2 C23.2 FB2.1 FB3.1 J2.1 J3.2 J3.4 J3.8 J4.2 J4.4 J4.8 Q1.5 R6.2 R7.2 R8.2 R9.2 R10.2 R12.2 R14.2 R22.2 R32.2 U2.D8 U2.E8 U3.17 U3.36 U3.44 | length 239.6
  L1-TOP w0.127: Q1.5@62.96,24.4 63.71,24.4 R22.2@63.86,24.55 64.41,24.55 66.66,22.3 69.2,22.3 70.72,20.78 v1(70.72,14.9)
  L1-TOP w0.152: U2.E8@68.5,9.475 68.6,9.575 v1(68.6,9.675) 68.6,9.775 U2.D8@68.5,9.875 U2.E8@68.5,9.475
  L1-TOP w0.2: J4.2@3.05,9.25 3.05,9.95 3.225,10.125 3.4,9.95 J4.4@3.4,9.25 ; 3.7,10.45 4.1,10.05 J4.8@4.1,9.25 ; 75,14.8 75,14.14 ; v1@75.16,14.8 75.71,14.8 R8.2@75.81,14.7 ; R10.2@75.41,13.7 75,14.11 75,14.14 ; R6.2@75.86,13.05 R7.2@75.16,13.05 74.71,13.05 74.66,13.1 ; v1(76.75,16.75) J2.1@77.66,16.75 ; U3.36@77.2,4.8 76.405,4.8 C13.2@76.3,4.695 76.195,4.8 75.96,4.8 75.035,5.725 75.035,10.625 74.66,11 74.66,13.1 ; R9.2@80.85,1.9 80.95,1.8 v1(82,1.8) ; U3.44@81.375,4.125 81.375,3.725 81.7,3.4 C11.2@81.7,3.03 ; U3.17@81.375,10.975 81.375,11.65 81.625,11.9 81.625,12.12 C12.2@81.655,12.15 ; C12.2@81.655,12.18 C12.2@81.655,12.15 ; C11.2@81.845,2.955 81.895,2.955 82.16,2.69 82.2,2.65 82.2,1.8 ; R12.2@82.575,12.15 81.795,12.15 81.725,12.22 C12.2@81.655,12.15 ; J3.2@116.25,8.75 116.25,8.075 116.375,7.95 116.6,7.95 J3.4@116.6,8.75 ; 117.11,7.95 117.3,8.14 J3.8@117.3,8.75 ; 74.66,13.1 74.66,13.8 75,14.14
  L1-TOP w0.3: v1(74.8,14.8) 74.96,14.8 75,14.8 v1@75.16,14.8 ; C12.2@81.755,12.15 v1(81.755,12.475) ; v1(82,1.8) 82.2,1.8 v1(82.4,1.8) ; R12.2@82.575,12.15 v1(82.575,12.475) ; v1(86.46,12.4) v1(86.86,12.4) v1(87.26,12.4) 87.26,10 88.11,9.15 C10.2@88.11,8.6 89.215,8.6 FB2.1@89.36,8.455 90.26,7.555 90.26,6.16 88.76,4.66 88.76,3.6 ; R14.2@89.46,3.55 88.81,3.55 88.76,3.6 ; 116.6,7.95 117.11,7.95 v1(117.56,7.5) v1(117.96,7.5) v1(118.36,7.5) ; 48.66,12.825 v1(49.06,13.225) v1(48.66,13.225) ; 48.66,12.825 v1(48.66,13.225) ; 48.66,12.825 v1(48.26,13.225) v1(48.66,13.225) ; 70.1,13.6 v1(69.9,13.6) v1(69.9,13.2) v1(70.3,13.6) ; 70.1,13.6 v1(70.3,13.6) ; 70.1,13.6 70.72,14.22 ; v1(70.3,13.6) 70.8,14.1 ; 70.72,14.22 70.72,14.18 70.8,14.1 ; 70.72,14.22 v1(70.72,14.9) ; 70.72,14.22 71.06,14.56 ; v1(70.72,14.9) v1(71.16,14.9) ; v1(70.72,14.9) 70.96,14.66 ; 70.8,14.1 71.16,14.46 ; 70.96,14.66 v1@71.16,14.86 ; 70.96,14.66 71.06,14.56 ; 71.06,14.56 71.16,14.66 ; 71.06,14.56 71.16,14.46 ; 71.16,14.46 v1(71.6,14.9) v1(71.16,14.9) ; 71.16,14.46 71.16,14.66 ; 71.16,14.66 v1@71.16,14.86 ; v1@71.16,14.86 v1(71.16,14.9) ; v1@83.9,1.9 83.5,1.9 v1(83.4,1.8) v1(83.8,1.8) v1@83.9,1.9 ; v1@83.9,1.9 88.56,1.9 88.76,2.1 88.76,3.6
  L1-TOP w0.4: 3.225,9.975 3.7,10.45 3.7,12.2 4.865,13.365 v1(18.5,13.365) v1(18.9,13.365) v1(19.3,13.365) v1(19.7,13.365)
  L1-TOP w0.5: R32.2@48.66,11.8 48.66,12.825
  L4-BOT w0.2: C22.2@68.46,10.95 68.54,10.87 C23.2@68.54,10.2 68.6,10.14 v1(68.6,9.675) ; 76.75,15.25 v1(76.75,16.75)
  L4-BOT w0.3: 48.12,13.365 v1(48.26,13.225) v1(48.66,13.225) v1(49.06,13.225) 49.2,13.365 ; C22.2@68.46,10.95 68.46,11.445 FB3.1@69.215,12.2 69.525,12.51 69.525,13.025 69.9,13.4 ; 70.42,15.2 v1(70.72,14.9) v1(71.16,14.9) v1(71.6,14.9) 71.9,15.2 ; 74.4,15.2 v1(74.8,14.8) ; 75.2,15.2 v1(74.8,14.8) ; 75.6,15.2 v1(75.2,14.8) v1(74.8,14.8) ; v1(82,1.8) v1(82.4,1.8) v1(83.4,1.8) v1(83.8,1.8) ; v1(86.46,12.4) v1(86.86,12.4) v1(87.26,12.4) ; v1(117.56,7.5) v1(117.96,7.5) v1(118.36,7.5) 118.7,7.5 119.225,6.975 119.225,5.775 119.7,5.3 121.6,5.3 122.3,4.6 ; 69.9,13.4 v1(69.9,13.2) v1(70.3,13.6) v1(69.9,13.6) 69.9,13.4
  L4-BOT w0.4: v1(18.5,13.365) 48.12,13.365 49.2,13.365 49.635,13.8 60.6,13.8 62,15.2 70.42,15.2 71.9,15.2 74.4,15.2 75.2,15.2 75.6,15.2 77.9,15.2 80.625,12.475 v1(82.575,12.475) 93.475,12.475 94.4,13.4 124,13.4 126.6,10.8 126.6,6.7 125.475,5.575 124.375,5.575 123.4,4.6 122.3,4.6
1V8_ANA: C14.2 C15.2 C16.2 C17.2 FB2.2 U3.4 U3.6 | length 9.3
  L1-TOP w0.2: U3.4@84.05,6.3 85.045,6.3 85.125,6.22 85.255,6.35 86.875,6.35 C16.2@87.025,6.5 ; U3.6@84.05,7.274 U3.6@84.05,7.3 84.6,7.3 84.75,7.45 85.82,7.45 C17.2@85.9,7.53 85.98,7.45 86.325,7.45 86.45,7.325 86.45,6.825 86.575,6.7 C16.2@87,6.7
  L1-TOP w0.3: C16.2@87.1,6.55 C14.2@88.1,6.55 ; C14.2@88.225,6.425 C14.2@88.1,6.55 ; FB2.2@89.36,6.745 89.165,6.55 C14.2@88.1,6.55
1V8_AVDD: C18.2 C19.2 FB3.2 U2.C5 U2.C6 U2.C7 U2.G3 U2.G4 U2.G5 | length 6.8
  L1-TOP w0.152: U2.G3@66.5,8.675 U2.G4@66.9,8.675 U2.G5@67.3,8.675 ; U2.C5@67.3,10.275 U2.C6@67.7,10.275 U2.C7@68.1,10.275
  L4-BOT w0.2: v1(67.1,8.675) 66.585,8.675 C18.2@66.56,8.7 66.66,8.8 66.66,10.425 66.915,10.68 C19.2@67.01,10.68 ; v1(67.5,10.275) 67.095,10.68 C19.2@67.01,10.68 ; FB3.2@67.505,12.2 67.505,12.105 67.01,11.61 C19.2@67.01,10.68
1V8_BUCK: C43.2 C44.2 L3.2 R32.1 R33.2 U6.5 | length 11.8
  L1-TOP w0.1: L3.2@46.625,11.2 46.625,10.635 46.96,10.3 L3.2@47.01,10.3
  L1-TOP w0.2: R33.2@48.86,7.65 50.01,7.65 50.36,8 50.36,9.5 C44.2@49.56,10.3
  L1-TOP w0.25: L3.2@46.525,11.2 46.525,11.165 L3.2@46.56,11.2 ; L3.2@46.625,11.2 47.01,10.815 47.01,10.3 U6.5@47.01,8.995
  L1-TOP w0.3: C44.2@49.56,10.3 C44.2@49.66,10.4
  L1-TOP w0.5: L3.2@47.11,10.4 C43.2@48.26,10.4 ; C43.2@48.26,10.3 C44.2@49.56,10.3 ; C44.2@49.66,10.4 R32.1@49.66,11.8
1V_AVDD: C20.2 C21.2 FB1.2 U2.D4 U2.E4 U2.G6 U2.G7 | length 7.5
  L1-TOP w0.152: U2.G6@67.7,8.675 U2.G7@68.1,8.675 ; U2.E4@66.9,9.475 67,9.575 v1(67,9.675) 67,9.775 U2.D4@66.9,9.875 U2.E4@66.9,9.475
  L4-BOT w0.2: v1(67,9.675) 67,9.26 67.36,8.9 68.06,8.9 68.46,9.3 69.06,9.3 C20.2@69.16,9.4
  L4-BOT w0.3: v1(67.9,8.675) 67.9,8.84 67.91,8.85 ; C20.2@69.16,9.4 69.18,9.38 C21.2@69.18,8.8 69.18,6.335 FB1.2@69.215,6.3
1V_BUCK: C31.2 C32.2 L2.2 R24.1 R25.2 U4.5 | length 10.7
  L1-TOP w0.2: C32.2@48.36,4.4 C32.2@48.46,4.3 ; R25.2@48.86,1.65 50.01,1.65 50.36,2 50.36,3.5 C31.2@49.56,4.3
  L1-TOP w0.25: L2.2@46.825,5.2 47.01,5.015 47.01,4.4 U4.5@47.01,2.995
  L1-TOP w0.5: L2.2@47.01,4.4 48.26,4.4 C32.2@48.26,4.3 48.46,4.3 C31.2@49.56,4.3 R24.1@49.56,5.7
3V3: R1.2 R16.2 R17.2 R23.1 | length 26.5
  L1-TOP w0.127: v1(60,19.84) R1.2@60.46,19.84
  L1-TOP w0.15: R23.1@60.46,24.55 59.81,24.55 59.56,24.3 58.06,24.3 57.46,23.7 57.46,17.14 58,16.6 59.6,16.6 v1(60,16.2) 60.5,15.7 R17.2@60.56,15.7 ; R17.2@60.5,15.9 R17.2@60.56,15.9
  L1-TOP w0.3: R16.2@54.225,11.89 58.09,11.89 60.56,14.36 R17.2@60.56,15.7
  L4-BOT w0.15: v1(60,16.2) v1(60,19.84)
5V: C5.1 C28.2 C33.2 C42.2 C45.2 C46.2 C47.2 C48.2 C57.2 C60.2 C61.2 C62.2 CON2.1 D1.A D6.A L1.1 L5.1 L6.1 R31.1 U4.1 U4.8 U5.5 U5.6 U6.1 U6.8 U7.1 U7.20 U8.1 U8.20 U9.1 U9.3 | length 182.1
  L1-TOP w0.2: 43.06,6.8 45.51,6.8 U6.1@45.51,7.005 ; 43.3,3.3 43.3,1.26 43.76,0.8 45.51,0.8 U4.1@45.51,1.005 ; C5.1@53.275,6.05 53.275,5.6 53.525,5.35 54.625,5.35 55.15,5.875 U9.3@55.15,7.1
  L1-TOP w0.25: U4.1@45.51,0.785 U4.1@45.51,0.8 ; U6.1@45.51,6.785 U6.1@45.51,6.8
  L1-TOP w0.3: 93.9,7.3 90.96,4.36 90.96,3.3 91.26,3 96.85,3 97.725,2.125 99.129,2.125 U7.1@99.129,2.365 U7.1@99.129,2.8
  L1-TOP w0.4: D1.A@91.075,11.925 91.175,12.025 D6.A@91.175,12.7 91.775,13.3 92.5,13.3
  L1-TOP w0.5: U8.20@23.718,6.516 23.718,7.155 L6.1@27.1,7.155 ; U8.1@23.825,12.4 C60.2@24.71,12.4 24.71,12.91 24.925,13.125 28.332,13.125 ; 28.46,12.997 28.332,13.125 ; 35.632,13.125 28.332,13.125 ; 35.691,12.927 R31.1@35.691,11.92 35.325,11.554 35.325,10.508 36.355,9.478 ; 37.578,12.915 37.66,12.997 ; L1.1@40.65,10.508 L1.1@40.868,10.29 ; 43.2,3.4 43.3,3.3 C28.2@44.36,3.3 44.56,3.1 45.36,3.1 ; 43.2,9.3 C42.2@44.36,9.3 44.56,9.1 45.36,9.1 ; 52.36,14 52.2,13.84 52.2,6.4 52.55,6.05 C5.1@53.275,6.05 53.25,6.05 U9.1@53.25,7.1 ; C45.2@95.28,7.28 C45.2@95.3,7.3 ; C46.2@97.35,7.3 99.129,7.3 U7.20@99.129,8.5 ; 40.647,12.997 40.65,12.997 40.65,13 40.647,12.997
  L1-TOP w0.75: L6.1@27.1,6.9 28.46,6.9 C48.2@28.46,9.4 C47.2@28.46,11.2 28.46,12.997 ; 35.76,12.997 37.66,12.997 43.2,12.997 ; C33.2@37.578,11.932 37.578,12.915 ; L1.1@40.65,10.508 40.65,12.997 ; 43.2,3.4 43.2,9.3 43.2,12.997 ; 58.9,14.6 58.3,14.6 57.2,13.5 54.26,13.5 53.76,14 52.36,14 47.9,14 46.897,12.997 43.2,12.997 ; 92.5,13.3 93.4,13.3 93.4,7.8 93.9,7.3 C45.2@95.3,7.3 ; C45.2@95.3,7.3 C46.2@97.35,7.3 97.35,9.7 L5.1@96.2,9.7 95.3,9.7 C45.2@95.3,7.3
  L1-TOP w1.2: C61.2@72.2,25.6 C62.2@74.4,25.6 CON2.1@76.99,25.6
  L4-BOT w0.75: 58.3,14.6 60.2,14.6 61.575,15.975 69.675,15.975 76.99,23.29 ; CON2.1@76.99,25.6 76.99,23.29 ; 93.1,13.3 80.9,13.3 80.025,14.175 80.025,20.255 76.99,23.29
  other v1: 92.4,13.1 92.8,13.1 93.2,13.1 92.4,13.5 92.8,13.5 93.2,13.5 58.2,14.4 58.6,14.4 59,14.4 58.2,14.8 58.6,14.8 59,14.8
5V7: J3.3 J4.3 R18.2 | length 132.2
  L1-TOP w0.2: J4.3@3.4,7.25 3.4,4.8 5,3.2 v1(5,1.4) ; J3.3@116.6,6.75 116.6,1.1 117,0.7 v1(117.3,0.7)
  L1-TOP w0.3: v1(5,1.4) v1(5.3,1.1) v1(5.6,0.8) ; 39.854,0.854 v1(39.5,0.5) v1(39.9,0.5) v1(40.3,0.5) 39.946,0.854 39.925,0.875 ; v1@39.925,0.516 39.925,0.7 39.925,0.875 ; 39.946,0.894 39.925,0.916 39.925,0.875 ; v1(117.3,0.7) v1(117.7,0.7) v1(118.1,0.7)
  L1-TOP w0.5: 39.925,0.7 39.946,0.721 39.946,0.854 39.946,0.894 R18.2@39.946,2.446
  L4-BOT w0.3: v1(5,1.4) v1(5.3,1.1) 5.9,0.5 117.1,0.5 v1(117.3,0.7) v1(117.7,0.7) v1(118.1,0.7)
36V_BL_L: C49.1 C51.2 C52.2 D4.K J3.41 R35.1 | length 42.1
  L1-TOP w0.2: 100.96,12.06 R35.1@100.96,10.65 101.74,10.65 C49.1@101.76,10.63 ; C51.2@106.56,12.6 C51.2@106.76,12.8 ; J3.41@123.25,6.75 123.25,6.01 123.96,5.3 126.26,5.3 127.3,6.34 127.3,11.26 127.18,11.38
  L1-TOP w0.5: D4.K@99.5,12.15 100.9,12.15 101.35,12.6 C52.2@104.26,12.6 C51.2@106.56,12.6 107,12.6 107.8,13.4 125.15,13.4 127.175,11.375
36V_BL_R: C50.1 C53.2 C54.2 D5.K J4.41 R36.1 | length 19.3
  L1-TOP w0.2: J4.41@10.05,7.25 10.05,6.95 11.2,5.8 12.1,5.8 12.2,5.7 ; C50.1@21.06,3.75 R36.1@21.86,3.75 21.86,2.15 21.9,2.15 ; D5.K@23.5,1.95 D5.K@23.5,2
  L1-TOP w0.5: 12.2,5.7 13.1,4.8 13.1,3.5 14.8,1.8 C54.2@16.16,1.8 C53.2@18.46,1.8 18.81,2.15 21.86,2.15 D5.K@23.5,2.15
-5V7: J3.7 J4.7 R19.2 | length 129.1
  L1-TOP w0.2: J4.7@4.1,7.25 4.1,4.8 5.5,3.4 v1(5.5,1.8) ; v1(117.3,1.3) J3.7@117.3,6.75
  L1-TOP w0.3: v1(5.5,1.8) v1(6.1,1.2) ; v1(117.3,1.3) v1(117.7,1.3) v1(118.1,1.3) ; v1(34.45,0.925) 34.45,1.1 R19.2@34.45,1.325 ; v1(34.45,0.925) v1(34.85,0.925) 34.454,1.321 34.454,1.329 R19.2@34.45,1.325 ; v1(34.45,0.925) v1(34.05,0.925) R19.2@34.45,1.325
  L1-TOP w0.5: 34.45,1.1 34.454,1.104 R19.2@34.454,1.321 ; R19.2@34.454,1.329 R19.2@34.454,1.646
  L4-BOT w0.3: v1(5.5,1.8) 6.375,0.925 116.625,0.925 117,1.3 v1(117.7,1.3) v1(118.1,1.3)
  other v1: 5.8,1.5
ANX_HPD: Q1.4 R22.1 U2.D9 | length 20.2
  L1-TOP w0.076: R22.1@63.86,23.85 64.65,23.85 66.5,22 69,22 70.2,20.8 70.2,14.6 69.5,13.9 69.5,12.04 68.7,11.24 68.7,10.075 U2.D9@68.9,9.875
  L1-TOP w0.152: Q1.4@62.96,23.9 63.81,23.9 R22.1@63.86,23.85
ANX_I2C_SCL: J2.9 R7.1 U2.D10 U3.32 | length 25.8
  L1-TOP w0.076: U2.D10@69.3,9.875 69.575,9.875 70.1,10.4 71.56,10.4 v1(72.56,11.4)
  L1-TOP w0.1: v1(72.56,11.4) 73.06,11.4 73.16,11.5 73.16,17.86 76.05,20.75 J2.9@77.66,20.75
  L1-TOP w0.125: R7.1@75.16,12.35 v1(75.16,11.4) 75.335,11.225 75.335,8.325 76.86,6.8 U3.32@77.2,6.8
  L4-BOT w0.125: v1(72.56,11.4) v1(75.16,11.4)
ANX_I2C_SDA: J2.11 R6.1 U2.C9 U3.31 | length 26.6
  L1-TOP w0.076: U2.C9@68.9,10.275 69.1,10.075 69.475,10.075 70,10.6 71.36,10.6 72.46,11.7 v1(72.86,11.7)
  L1-TOP w0.1: v1(72.86,11.7) 72.86,18.36 76.25,21.75 J2.11@77.66,21.75
  L1-TOP w0.125: R6.1@75.86,12.35 v1(75.86,11.7) 75.585,11.425 75.585,8.575 76.86,7.3 U3.31@77.2,7.3
  L4-BOT w0.127: v1(72.86,11.7) v1(75.86,11.7)
ANX_I2S_MCK: U2.B10 | length 0
ANX_I2S_SCK: U2.H8
ANX_I2S_SD: U2.E10
ANX_I2S_WS: U2.H7
ANX_INTP: J2.12 R8.1 U2.B4 U3.26 | length 30.1
  L1-TOP w0.076: v1(66.46,11.6) 66.7,11.36 66.7,10.875 U2.B4@66.9,10.675
  L1-TOP w0.1: R8.1@76.51,14.7 76.81,15 78.3,15 79.4,16.1 79.4,21.2 78.35,22.25 J2.12@77.66,22.25
  L1-TOP w0.127: R8.1@76.51,14.7 76.51,14.35 v1(76.76,14.1) 76.96,13.9 76.96,12.34 77.2,12.1 77.2,11.09 76.585,10.475 76.585,10.075 76.86,9.8 U3.26@77.2,9.8
  L4-BOT w0.127: v1(66.46,11.6) 66.46,13.3 67.26,14.1 v1(76.76,14.1)
ANX_MSDA: U2.A10 U3.28 | length 11.5
  L1-TOP w0.1: U2.A10@69.3,11.075 71.075,11.075 v1(72,12)
  L1-TOP w0.127: v1(76.4,11.2) 76.085,10.885 76.085,9.575 76.86,8.8 U3.28@77.2,8.8
  L4-BOT w0.127: v1(72,12) 72,11.36 72.26,11.1 75.7,11.1 75.8,11.2 v1(76.4,11.2)
ANX_PWEN: U2.B3 U3.25 | length 19
  L1-TOP w0.076: v1@66.06,11.54 v1(66.06,11.6) 66.3,11.36 66.3,10.875 U2.B3@66.5,10.675
  L1-TOP w0.127: v1(77.1,14.46) 77.26,14.3 77.26,12.44 77.46,12.24 77.46,10.3 U3.25@77.2,10.3
  L4-BOT w0.127: v1(66.06,11.6) 66.06,13.4 67.12,14.46 v1(77.1,14.46)
ANX_RESETN: U2.C10 U3.27 | length 11.6
  L1-TOP w0.076: U2.C10@69.3,10.275 69.825,10.8 71.26,10.8 72.46,12 v1(72.5,12)
  L1-TOP w0.127: v1(76.76,12) 76.76,10.975 76.335,10.55 76.335,9.825 76.86,9.3 U3.27@77.2,9.3
  L1-TOP w0.15: U3.27@77.175,9.325 U3.27@77.2,9.3
  L4-BOT w0.127: v1(72.5,12) v1(76.76,12)
ANX_XIN: C8.1 R20.1 U2.A2 Y1.1 | length 6.3
  L1-TOP w0.1: Y1.1@62.46,14.1 62.46,14.15 Y1.1@62.63,14.32 ; C8.1@62.67,15 62.67,14.32 Y1.1@62.5,14.15 63.15,13.5 63.9,13.5 64.3,13.1 R20.1@64.3,12.75 64.3,12.7 64.425,12.575 64.6,12.575 U2.A2@66.1,11.075
ANX_XOUT: C7.1 R20.2 U2.A1 Y1.3 | length 4
  L1-TOP w0.1: C7.1@63.29,12 63.29,12.68 63.46,12.85 Y1.3@63.56,12.75 ; Y1.3@63.475,12.825 R20.2@64.275,12.025 ; R20.2@64.3,12.05 64.725,12.05 U2.A1@65.7,11.075
AUX_N: C3.1 U2.D3 | length 9
  L1-TOP w0.076: C3.1@64.49,16.1 64.714,16.324 64.976,16.324 65.5,15.8 65.5,14.276 65.3,14.076 65.084,14.076 v1(64.96,14.2)
  L1-TOP w0.125: v2(66.35,10.025) U2.D3@66.5,9.875
  L4-BOT w0.076: v1(64.96,14.2) 65.084,14.076 65.399,14.076 65.612,13.863 65.612,11.163 65.86,10.916 65.86,10.101 66.06,9.901 66.226,9.901 v2(66.35,10.025)
AUX_P: C2.1 U2.E3 | length 9.5
  L1-TOP w0.076: C2.1@64.49,16.7 64.714,16.476 65.039,16.476 65.652,15.863 65.652,14.213 65.363,13.924 65.084,13.924 v1(64.96,13.8)
  L1-TOP w0.125: v2(66.35,9.625) U2.E3@66.5,9.475
  L4-BOT w0.076: v1(64.96,13.8) 65.084,13.924 65.336,13.924 65.46,13.8 65.46,11.1 65.708,10.852 65.708,10.038 65.997,9.749 66.226,9.749 v2(66.35,9.625)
